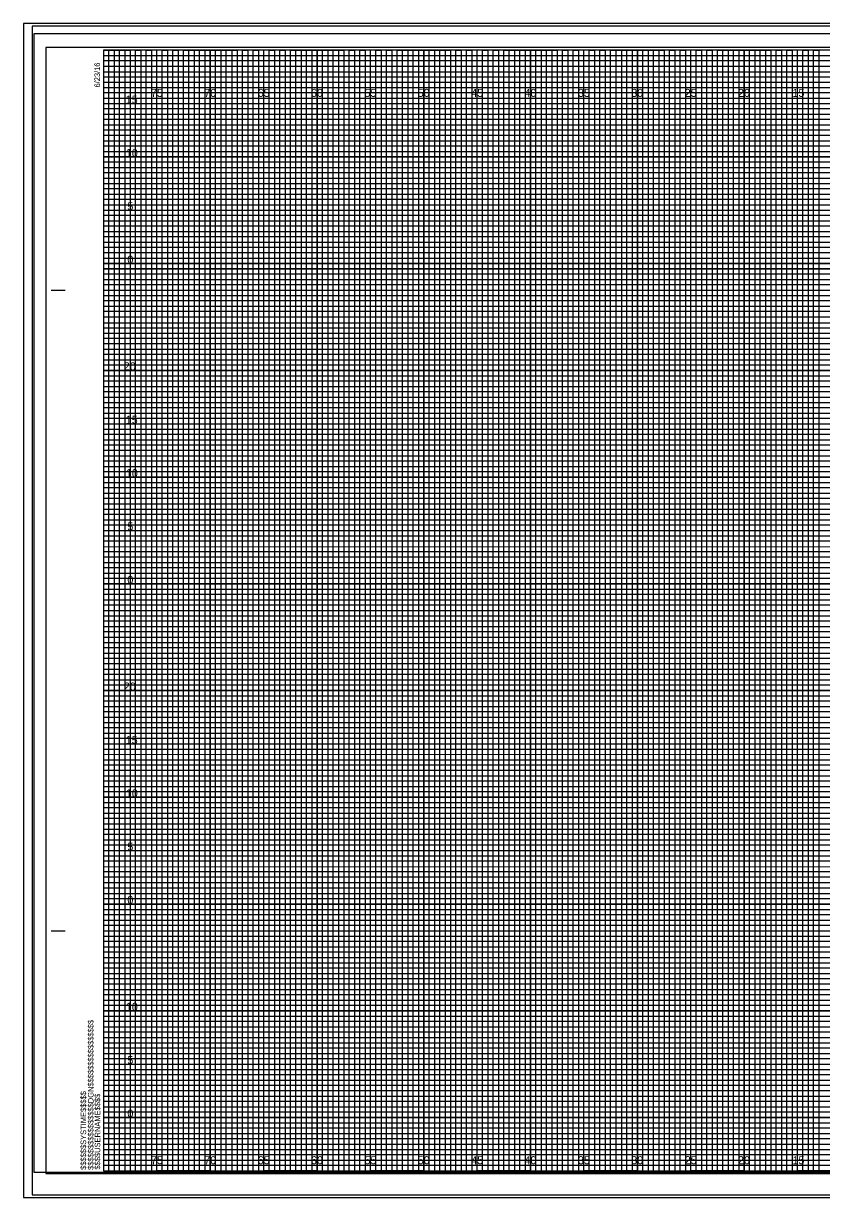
# Model space of a CAD drawing. Extents: x -8 to 162, y -2 to 108.
import ezdxf

# ---------------------------------------------------------------- set-up
doc = ezdxf.new("R2010")
doc.units = 0
for name, color, linetype in [('Prop XS Elevation Labels', 7, 'Continuous'), ('Prop XS Offset Labels', 7, 'Continuous'), ('Sheet Cross Section CELL', 7, 'Continuous'), ('Sheet Cross Section Grid Major CELL', 7, 'Continuous'), ('Sheet Cross Section Grid Middle CELL', 7, 'Continuous'), ('Sheet Cross Section Grid Minor 1 CELL', 7, 'Continuous'), ('Sheet Cross Section Grid Minor 2 CELL', 7, 'Continuous'), ('Sheet Cutting Line CELL', 7, 'Continuous'), ('Sheet DOT Grid CELL', 7, 'Continuous'), ('Sheet Plot Border Inside CELL', 7, 'Continuous'), ('Sheet Plot Border Outside CELL', 7, 'Continuous'), ('Stewart Plot Border DJ1055', 7, 'Continuous'), ('Stewart Plot Border DJ1055 Invisible', 7, 'Continuous'), ('Stewart Plot Border Xerox6279 and LJ5000', 7, 'Continuous')]:
    doc.layers.add(name, color=color, linetype=linetype)

msp = doc.modelspace()

# ---------------------------------------------------------------- linework, layer by layer
at = {"layer": 'Sheet Cross Section CELL'}
for p, q in [((-4.9, 82.5), (-3.65, 82.5)), ((-4.85, 82.5), (-3.6, 82.5)), ((-4.9, 22.5), (-3.65, 22.5)), ((-4.85, 22.5), (-3.6, 22.5)), ((0, 0), (0, 0)), ((0, 0), (0, 0)), ((0, 0), (0, 0)), ((0, 0), (0, 0)), ((0, 0), (0, 0)), ((0, 0), (0, 0)), ((0, 0), (0, 0))]:
    msp.add_line(p, q, dxfattribs=at)
msp.add_lwpolyline([(160, 105), (0, 105), (0, 0), (160, 0)], close=True, dxfattribs=at)
at = {"layer": 'Sheet Cross Section Grid Major CELL'}
for p, q in [((5, 105), (0, 105)), ((5, 0), (5, 105)), ((15, 105), (10, 105)), ((10, 105), (10, 0)), ((15, 0), (15, 105)), ((25, 105), (20, 105)), ((20, 105), (20, 0)), ((25, 0), (25, 105)), ((35, 105), (30, 105)), ((30, 105), (30, 0)), ((35, 0), (35, 105)), ((45, 105), (40, 105)), ((40, 105), (40, 0)), ((45, 0), (45, 105)), ((55, 105), (50, 105)), ((50, 105), (50, 0)), ((55, 0), (55, 105)), ((65, 105), (60, 105)), ((60, 105), (60, 0)), ((65, 0), (65, 105)), ((10, 0), (5, 0)), ((20, 0), (15, 0)), ((30, 0), (25, 0)), ((40, 0), (35, 0)), ((50, 0), (45, 0)), ((60, 0), (55, 0)), ((70, 0), (65, 0))]:
    msp.add_line(p, q, dxfattribs=at)
for points in [[(0, 100), (160, 100), (160, 95), (0, 95)], [(0, 90), (160, 90), (160, 85), (0, 85)], [(0, 80), (160, 80), (160, 75), (0, 75)], [(0, 70), (160, 70), (160, 65), (0, 65)], [(0, 60), (160, 60), (160, 55), (0, 55)], [(0, 50), (160, 50), (160, 45), (0, 45)], [(0, 40), (160, 40), (160, 35), (0, 35)], [(0, 30), (160, 30), (160, 25), (0, 25)], [(0, 20), (160, 20), (160, 15), (0, 15)], [(0, 10), (160, 10), (160, 5), (0, 5)]]:
    msp.add_lwpolyline(points, dxfattribs=at)
at = {"layer": 'Sheet Cross Section Grid Middle CELL'}
for points in [[(0, 105), (2.5, 105), (2.5, 0), (7.5, 0), (7.5, 105), (12.5, 105), (12.5, 0), (17.5, 0), (17.5, 105), (22.5, 105), (22.5, 0), (27.5, 0), (27.5, 105), (32.5, 105), (32.5, 0), (37.5, 0), (37.5, 105), (42.5, 105), (42.5, 0), (47.5, 0), (47.5, 105), (52.5, 105), (52.5, 0), (57.5, 0), (57.5, 105), (62.5, 105), (62.5, 0), (67.5, 0)], [(0, 102.5), (137.5, 102.5)], [(0, 92.5), (160, 92.5), (160, 97.5), (0, 97.5)], [(0, 82.5), (160, 82.5), (160, 87.5), (0, 87.5)], [(0, 72.5), (160, 72.5), (160, 77.5), (0, 77.5)], [(0, 62.5), (160, 62.5), (160, 67.5), (0, 67.5)], [(0, 52.5), (160, 52.5), (160, 57.5), (0, 57.5)], [(0, 42.5), (160, 42.5), (160, 47.5), (0, 47.5)], [(0, 32.5), (160, 32.5), (160, 37.5), (0, 37.5)], [(0, 22.5), (160, 22.5), (160, 27.5), (0, 27.5)], [(0, 12.5), (160, 12.5), (160, 17.5), (0, 17.5)], [(0, 2.5), (160, 2.5), (160, 7.5), (0, 7.5)]]:
    msp.add_lwpolyline(points, dxfattribs=at)
at = {"layer": 'Sheet Cross Section Grid Minor 1 CELL'}
for p, q in [((0, 104.5), (130, 104.5)), ((130, 103.99), (0, 103.99)), ((0, 103.99), (0, 103.5)), ((0, 103.5), (130, 103.5)), ((130, 102.95), (0, 102.95)), ((0, 102.95), (0, 102)), ((0, 102), (160, 102))]:
    msp.add_line(p, q, dxfattribs=at)
for points in [[(0, 101.5), (135, 101.5), (160, 101.5), (160, 101), (0, 101)], [(0, 100.5), (160, 100.5), (160, 99.5), (0, 99.5)], [(0, 99), (160, 99), (160, 98.5), (0, 98.49)], [(0, 98), (160, 98), (160, 97), (0, 97)], [(0, 96.5), (160, 96.5), (160, 96), (0, 96)], [(0, 95.5), (160, 95.5), (160, 94.5), (0, 94.5)], [(0, 94), (160, 94), (160, 93.5), (0, 93.5)], [(0, 93), (160, 93), (160, 92), (0, 92)], [(0, 91.5), (160, 91.5), (160, 91), (0, 91)], [(0, 90.5), (160, 90.5), (160, 89.5), (0, 89.5)], [(0, 89), (160, 89), (160, 88.5), (0, 88.5)], [(0, 88), (160, 88), (160, 86.98), (160, 86.5), (160, 86), (0, 86)], [(0, 87), (160, 87), (160, 86.5), (0, 86.5)], [(0, 85.5), (160, 85.5), (160, 84.5), (0, 84.52)], [(0, 84.52), (160, 84.5), (160, 84), (0, 84)], [(0, 83.5), (160, 83.5), (160, 83), (0, 83)], [(0, 82), (160, 82), (160, 81.5), (0, 81.5)], [(0, 81), (160, 81), (160, 80.5), (0, 80.5)], [(-0.04, 79.45), (160, 79.45), (160, 78.94), (-0.04, 78.94)], [(0, 78.5), (160, 78.5), (160, 78), (0, 78)], [(0, 77), (160, 77), (160, 76.5), (0, 76.5)], [(0, 76), (160, 76), (160, 75.5), (0, 75.5)], [(0, 74.5), (160, 74.5), (160, 74), (0, 74)], [(0, 73.5), (160, 73.5), (160, 73), (0, 73)], [(0, 72), (160, 72), (160, 71.5), (0, 71.5)], [(0, 71), (160, 71), (160, 70.5), (0, 70.5)], [(0, 69.5), (160, 69.5), (160, 68.99), (0, 69)], [(0, 68.5), (160, 68.5), (160, 68), (0, 68)], [(0, 67), (160, 67), (160, 66.5), (0, 66.5)], [(0, 66), (160, 66), (160, 65.5), (0, 65.5)], [(0, 64.5), (160, 64.5), (160, 64), (0, 64)], [(0, 63.5), (160, 63.5), (160, 63), (0, 63)], [(0, 62), (160, 62), (160, 61.5), (0, 61.5)], [(0, 61), (160, 61), (160, 60.5), (0, 60.5)], [(0, 59.5), (160, 59.5), (160, 59), (0, 59)], [(0, 58.5), (160.03, 58.45), (160, 58), (0, 58)], [(0, 57), (160, 57), (160, 56.5), (0, 56.5)], [(0, 56), (160, 56), (160, 55.5), (0, 55.5)], [(0, 54.5), (160, 54.5), (160, 54), (0, 54)], [(0, 53.5), (160, 53.5), (160, 53), (0, 53)], [(0, 52), (160, 52), (160, 51.5), (0, 51.5)], [(0, 51), (160, 51), (160, 50.5), (0, 50.5)], [(0, 49.5), (160, 49.5), (160, 49), (0, 49)], [(0, 48.5), (160, 48.5), (160, 48), (0, 48)], [(0, 47), (160, 47), (160, 46.5), (0, 46.5)], [(0, 46), (160, 46), (160, 45.5), (0, 45.5)], [(0, 44.5), (160, 44.5), (160, 44), (0, 44)], [(0, 43.5), (160, 43.5), (160, 43), (0, 43)], [(0, 42), (160, 42), (160, 41.5), (0, 41.5)], [(0, 41), (160, 41), (160, 40.5), (0, 40.5)], [(0, 39.5), (160, 39.5), (160, 38.99), (0, 39)], [(0, 38.5), (160, 38.5), (160, 38), (0, 38)], [(0, 37), (160, 37), (160, 36.5), (0, 36.5)], [(0, 36), (160, 36), (160, 35.5), (0, 35.5)], [(0, 34.5), (160, 34.5), (160, 34), (0, 34)], [(0, 33.5), (160, 33.5), (160, 33), (0, 33)], [(0, 32), (160, 32), (160, 31.5), (0, 31.5)], [(0, 31), (160, 31), (160, 30.5), (0, 30.5)], [(0, 29.5), (160, 29.5), (160, 29), (0, 29)], [(0, 28.5), (160.03, 28.46), (160, 28), (0, 28)], [(0, 27), (160, 27), (160, 26.5), (0, 26.5)], [(0, 26), (160, 26), (160, 25.5), (0, 25.5)], [(0, 24.5), (160, 24.5), (160, 24), (0, 24)], [(0, 23.5), (160, 23.5), (160, 23), (0, 23)], [(0, 22), (160, 22), (160, 21.5), (0, 21.5)], [(0, 21), (160, 21), (160, 20.5), (0, 20.5)], [(0, 19.5), (160, 19.5), (160, 19), (0, 19)], [(0, 18.5), (160, 18.5), (160, 18), (0, 18)], [(0, 17), (160, 17), (160, 16.5), (0, 16.5)], [(0, 16), (160, 16), (160, 15.5), (0, 15.5)], [(0, 14.5), (160, 14.5), (160, 14), (0, 14)], [(0, 13.5), (160, 13.5), (160, 13), (0, 13)], [(0, 12), (160, 12), (160, 11.5), (0, 11.5)], [(0, 11), (160, 11), (160, 10.5), (0, 10.5)], [(0, 9.5), (160, 9.5), (160, 9), (0, 9)], [(0, 8.5), (160, 8.5), (160, 8), (0, 8)], [(0, 7), (160, 7), (160, 6.5), (0, 6.5)], [(0, 6), (160, 6), (160, 5.5), (0, 5.5)], [(0, 4.5), (160, 4.5), (160, 4), (0, 4)], [(0, 3.5), (160, 3.5), (160, 3), (0, 3)], [(0, 2), (160, 2), (160, 1.5), (0, 1.5)], [(0, 1), (160, 1), (160, 0.5), (0, 0.5)]]:
    msp.add_lwpolyline(points, dxfattribs=at)
at = {"layer": 'Sheet Cross Section Grid Minor 2 CELL'}
for points in [[(0, 0), (0.5, 0), (0.5, 105), (1, 105), (1, 0)], [(1, 0), (1.5, 0), (1.5, 105), (2, 105), (2, 0)], [(2.5, 0), (3, 0), (3, 105), (3.5, 105), (3.5, 0)], [(3.5, 0), (4, 0), (4, 105), (4.5, 105), (4.5, 0)], [(5, 0), (5.5, 0), (5.5, 105), (6, 105), (6, 0)], [(6, 0), (6.5, 0), (6.5, 105), (7, 105), (7, 0)], [(7.5, 0), (8, 0), (8, 105), (8.5, 105), (8.5, 0)], [(8.5, 0), (9, 0), (9, 105), (9.5, 105), (9.5, 0)], [(10, 0), (10.5, 0), (10.5, 105), (11, 105), (11, 0)], [(11, 0), (11.5, 0), (11.5, 105), (12, 105), (12, 0)], [(12.5, 0), (13, 0), (13, 105), (13.5, 105), (13.5, 0)], [(13.5, 0), (14, 0), (14, 105), (14.5, 105), (14.5, 0)], [(15, 0), (15.5, 0), (15.5, 105), (16, 105), (16, 0)], [(16, 0), (16.5, 0), (16.5, 105), (17, 105), (17, 0)], [(17.5, 0), (18, 0), (18, 105), (18.5, 105), (18.5, 0)], [(18.5, 0), (19, 0), (19, 105), (19.5, 105), (19.5, 0)], [(20, 0), (20.5, 0), (20.5, 105), (21, 105), (21, 0)], [(21, 0), (21.5, 0), (21.5, 105), (22, 105), (22, 0)], [(22.5, 0), (23, 0), (23, 105), (23.5, 105), (23.5, 0)], [(23.5, 0), (24, 0), (24, 105), (24.5, 105), (24.5, 0)], [(25, 0), (25.5, 0), (25.5, 105), (26, 105), (26, 0)], [(26, 0), (26.5, 0), (26.5, 105), (27, 105), (27, 0)], [(27.5, 0), (28, 0), (28, 105), (28.5, 105), (28.5, 0)], [(28.5, 0), (29, 0), (29, 105), (29.5, 105), (29.5, 0)], [(30, 0), (30.5, 0), (30.5, 105), (31, 105), (31, 0)], [(31, 0), (31.5, 0), (31.5, 105), (32, 105), (32, 0)], [(32.5, 0), (33, 0), (33, 105), (33.5, 105), (33.5, 0)], [(33.5, 0), (34, 0), (34, 105), (34.5, 105), (34.5, 0)], [(35, 0), (35.5, 0), (35.5, 105), (36, 105), (36, 0)], [(36, 0), (36.5, 0), (36.5, 105), (37, 105), (37, 0)], [(37.5, 0), (38, 0), (38, 105), (38.5, 105), (38.5, 0)], [(38.5, 0), (39, 0), (39, 105), (39.5, 105), (39.5, 0)], [(40, 0), (40.5, 0), (40.5, 105), (41, 105), (41, 0)], [(41, 0), (41.5, 0), (41.5, 105), (42, 105), (42, 0)], [(42.5, 0), (43, 0), (43, 105), (43.5, 105), (43.5, 0)], [(43.5, 0), (44, 0), (44, 105), (44.5, 105), (44.5, 0)], [(45, 0), (45.5, 0), (45.5, 105), (46, 105), (46, 0)], [(46, 0), (46.5, 0), (46.5, 105), (47, 105), (47, 0)], [(47.5, 0), (48, 0), (48, 105), (48.5, 105), (48.5, 0)], [(48.5, 0), (49, 0), (49, 105), (49.5, 105), (49.5, 0)], [(50, 0), (50.5, 0), (50.5, 105), (51, 105), (51, 0)], [(51, 0), (51.5, 0), (51.5, 105), (52, 105), (52, 0)], [(52.5, 0), (53, 0), (53, 105), (53.5, 105), (53.5, 0)], [(53.5, 0), (54, 0), (54, 105), (54.5, 105), (54.5, 0)], [(55, 0), (55.5, 0), (55.5, 105), (56, 105), (56, 0)], [(56, 0), (56.5, 0), (56.5, 105), (57, 105), (57, 0)], [(57.5, 0), (58, 0), (58, 105), (58.5, 105), (58.5, 0)], [(58.5, 0), (59, 0), (59, 105), (59.5, 105), (59.5, 0)], [(60, 0), (60.5, 0), (60.5, 105), (61, 105), (61, 0)], [(61, 0), (61.5, 0), (61.5, 105), (62, 105), (62, 0)], [(62.5, 0), (63, 0), (63, 105), (63.5, 105), (63.5, 0)], [(63.5, 0), (64, 0), (64, 105), (64.5, 105), (64.5, 0)], [(65, 0), (65.5, 0), (65.5, 105), (66, 105), (66, 0)], [(66, 0), (66.5, 0), (66.5, 105), (67, 105), (67, 0)]]:
    msp.add_lwpolyline(points, dxfattribs=at)
at = {"layer": 'Sheet Cutting Line CELL'}
for p, q in [((161.65, 107.25), (-6.7, 107.25)), ((-6.7, 107.25), (-6.7, -2.25)), ((-6.7, -2.25), (161.65, -2.25))]:
    msp.add_line(p, q, dxfattribs=at)
at = {"layer": 'Sheet DOT Grid CELL'}
for p, q in [((5, 0), (5, 105)), ((10, 0), (10, 105)), ((15, 0), (15, 105)), ((20, 0), (20, 105)), ((25, 0), (25, 105)), ((30, 0), (30, 105)), ((35, 0), (35, 105)), ((40, 0), (40, 105)), ((45, 0), (45, 105)), ((50, 0), (50, 105)), ((55, 0), (55, 105)), ((60, 0), (60, 105)), ((65, 0), (65, 105)), ((0, 100), (160, 100)), ((0, 95), (160, 95)), ((0, 90), (160, 90)), ((0, 85), (160, 85)), ((0, 80), (160, 80)), ((0, 75), (160, 75)), ((0, 70), (160, 70)), ((0, 65), (160, 65)), ((0, 60), (160, 60)), ((0, 55), (160, 55)), ((0, 50), (160, 50)), ((0, 45), (160, 45)), ((0, 40), (160, 40)), ((0, 35), (160, 35)), ((0, 30), (160, 30)), ((0, 25), (160, 25)), ((0, 20), (160, 20)), ((0, 15), (160, 15)), ((0, 10), (160, 10)), ((0, 5), (160, 5))]:
    msp.add_line(p, q, dxfattribs=at)
at = {"layer": 'Sheet Plot Border Inside CELL'}
msp.add_lwpolyline([(-5.4, -0.25), (161.2, -0.25), (161.2, 105.25), (-5.4, 105.25)], close=True, dxfattribs=at)
at = {"layer": 'Sheet Plot Border Outside CELL'}
msp.add_lwpolyline([(-6.7, -2.25), (161.65, -2.25), (161.65, 107.25), (-6.7, 107.25)], close=True, dxfattribs=at)
at = {"layer": 'Stewart Plot Border DJ1055'}
msp.add_lwpolyline([(161.52, 106.53), (-6.52, 106.53), (-6.52, -0.13), (161.52, -0.13)], close=True, dxfattribs=at)
at = {"layer": 'Stewart Plot Border DJ1055 Invisible'}
msp.add_lwpolyline([(161.52, 106.53), (-6.52, 106.53), (-6.52, -0.13), (161.52, -0.13)], close=True, dxfattribs=at)
at = {"layer": 'Stewart Plot Border Xerox6279 and LJ5000'}
msp.add_lwpolyline([(-7.5, -2.5), (162.5, -2.5), (162.5, 107.5), (-7.5, 107.5)], close=True, dxfattribs=at)

# ---------------------------------------------------------------- texts
at = {"layer": 'Prop XS Elevation Labels'}
for s, p in [('15', (2.08, 100)), ('10', (2.09, 95)), ('5', (2.23, 90)), ('0', (2.23, 85)), ('20', (1.9, 75)), ('15', (2.08, 70)), ('10', (2.09, 65)), ('5', (2.23, 60)), ('0', (2.23, 55)), ('20', (1.9, 45)), ('15', (2.08, 40)), ('10', (2.09, 35)), ('5', (2.23, 30)), ('0', (2.23, 25)), ('10', (2.09, 15)), ('5', (2.23, 10)), ('0', (2.23, 5))]:
    msp.add_text(s, height=0.75, dxfattribs=at).set_placement(p)
at = {"layer": 'Prop XS Offset Labels'}
for s, p in [('75', (4.44, 100.62)), ('70', (9.43, 100.62)), ('65', (14.44, 100.62)), ('60', (19.43, 100.62)), ('55', (24.44, 100.62)), ('50', (29.43, 100.62)), ('45', (34.44, 100.62)), ('40', (39.43, 100.62)), ('35', (44.44, 100.62)), ('30', (49.43, 100.62)), ('25', (54.44, 100.62)), ('20', (59.43, 100.62)), ('15', (64.53, 100.62)), ('75', (4.44, 0.62)), ('70', (9.43, 0.62)), ('65', (14.44, 0.62)), ('60', (19.43, 0.62)), ('55', (24.44, 0.62)), ('50', (29.43, 0.62)), ('45', (34.44, 0.62)), ('40', (39.43, 0.62)), ('35', (44.44, 0.62)), ('30', (49.43, 0.62)), ('25', (54.44, 0.62)), ('20', (59.43, 0.62)), ('15', (64.53, 0.62))]:
    msp.add_text(s, height=0.75, dxfattribs=at).set_placement(p)
at = {"layer": 'Sheet Cross Section CELL'}
for s, p in [('6/23/16', (-0.33, 101.5)), ('$$$$$$$$$$$$$$$$DGN$$$$$$$$$$$$$$$$', (-0.94, 0.09)), ('$$$$$$SYSTIME$$$$$', (-1.63, 0.09)), ('$$$$USERNAME$$$$', (-0.31, 0.12))]:
    msp.add_text(s, height=0.525, rotation=90, dxfattribs=at).set_placement(p)

doc.saveas('drawing.dxf')
